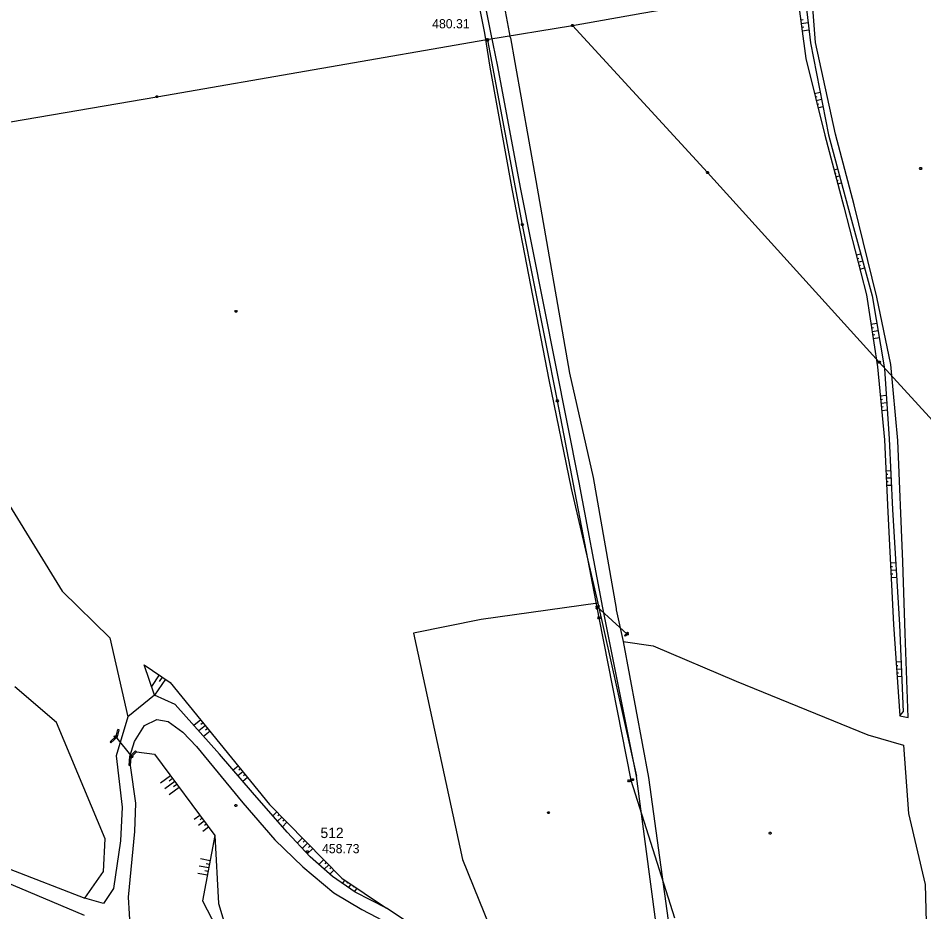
# Model space of a CAD drawing. Extents: x -664960 to -662754, y -993849 to -991145.
# Drawn here: x -664152.5 to -663855.3, y -993065.3 to -992772.1 of the extents above; entities that cross this region are included whole.
import ezdxf

# ---------------------------------------------------------------- set-up
doc = ezdxf.new("R2010")
doc.units = 0
for name, color, linetype in [('Vrstva 1', 7, 'Continuous'), ('Vrstva 13', 7, 'Continuous'), ('Vrstva 23', 7, 'Continuous'), ('Vrstva 24', 7, 'Continuous'), ('Vrstva 27', 7, 'Continuous'), ('Vrstva 37', 7, 'Continuous'), ('Vrstva 57', 7, 'Continuous'), ('Vrstva 63', 7, 'Continuous'), ('Vrstva 8', 7, 'Continuous')]:
    doc.layers.add(name, color=color, linetype=linetype)

msp = doc.modelspace()

# ---------------------------------------------------------------- linework, layer by layer
at = {"layer": 'Vrstva 13'}
for points in [[(-663856.195, -992821.143), (-663856.015, -992821.443), (-663856.195, -992821.743), (-663856.555, -992821.743), (-663856.735, -992821.443), (-663856.555, -992821.143), (-663856.195, -992821.143)], [(-664080.788, -992868.036), (-664080.608, -992868.336), (-664080.788, -992868.636), (-664081.148, -992868.636), (-664081.328, -992868.336), (-664081.148, -992868.036), (-664080.788, -992868.036)], [(-663978.312, -993032.479), (-663978.132, -993032.779), (-663978.312, -993033.079), (-663978.672, -993033.079), (-663978.852, -993032.779), (-663978.672, -993032.479), (-663978.312, -993032.479)], [(-663905.567, -993039.199), (-663905.387, -993039.499), (-663905.567, -993039.799), (-663905.927, -993039.799), (-663906.107, -993039.499), (-663905.927, -993039.199), (-663905.567, -993039.199)]]:
    msp.add_lwpolyline(points, dxfattribs=at)
at = {"layer": 'Vrstva 23'}
for points in [[(-663997.38, -992776.83), (-664005.01, -992738.66), (-664013.53, -992700.45), (-664027.03, -992643.59), (-664049.65, -992557.23), (-664058.31, -992527.13), (-664078.14, -992460.53), (-664096.77, -992402.28), (-664107.89, -992364.93), (-664112.84, -992348.94), (-664117.28, -992335.14), (-664119, -992322.82), (-664119, -992308.2)], [(-663990.89, -992778.63), (-663998.43, -992738.22), (-664009.08, -992695.49), (-664019.8, -992648.86), (-664043.31, -992556.7), (-664052, -992524.61), (-664073.04, -992455.33), (-664088.77, -992406.41), (-664100.89, -992363.53), (-664106.12, -992349.76), (-664111.81, -992331.24), (-664113.9, -992318.89), (-664113.87, -992308.88)], [(-663929.86, -993138.95), (-663931.93, -993130.37), (-663935.36, -993104.54), (-663943.29, -993068.58), (-663949.63, -993020.84), (-663960.66, -992965.6), (-663968.44, -992924.46), (-663987.68, -992827.67), (-663995.12, -992787.99), (-663997.38, -992776.83)], [(-663990.89, -992778.63), (-663989.48, -992786.64), (-663982.61, -992825.43), (-663971.53, -992888.56), (-663963.78, -992922.8), (-663956.22, -992965.82), (-663956.23, -992966.24), (-663953.96, -992976.6), (-663945.72, -993021.27), (-663939.17, -993068.14), (-663931.37, -993104), (-663922.1, -993138.98)]]:
    msp.add_lwpolyline(points, dxfattribs=at)
at = {"layer": 'Vrstva 24'}
for p, q in [((-663952.62, -992974.17), (-663962.52, -992965.24)), ((-664120.57, -993007.82), (-664115.13, -993014.42))]:
    msp.add_line(p, q, dxfattribs=at)
for points in [[(-663962.93, -992965.83), (-663961.97, -992964.76), (-663961.77, -992965.04), (-663962.65, -992966.03), (-663962.93, -992965.83)], [(-663962.855, -992965.342), (-663962.787, -992964.999), (-663962.453, -992964.897), (-663962.185, -992965.138), (-663962.253, -992965.481), (-663962.587, -992965.583), (-663962.855, -992965.342)], [(-663953.33, -992974.84), (-663953.59, -992974.69), (-663952.61, -992973.56), (-663952.29, -992973.72), (-663953.33, -992974.84)], [(-663952.955, -992974.272), (-663952.887, -992973.929), (-663952.553, -992973.827), (-663952.285, -992974.068), (-663952.353, -992974.411), (-663952.687, -992974.513), (-663952.955, -992974.272)], [(-664122.32, -993009.52), (-664120.25, -993007.7), (-664119.71, -993005.46)], [(-664122.32, -993009.52), (-664122.029, -993009.85), (-664119.855, -993007.938), (-664119.282, -993005.563), (-664119.71, -993005.46)], [(-664120.224, -993007.768), (-664120.341, -993008.098), (-664120.687, -993008.15), (-664120.916, -993007.872), (-664120.799, -993007.542), (-664120.453, -993007.49), (-664120.224, -993007.768)], [(-664115.56, -993017.28), (-664115.999, -993017.254), (-664115.829, -993014.333), (-664113.956, -993012.523), (-664113.65, -993012.84)], [(-664115.56, -993017.28), (-664115.4, -993014.53), (-664113.65, -993012.84)], [(-664114.784, -993014.368), (-664114.901, -993014.698), (-664115.247, -993014.75), (-664115.476, -993014.472), (-664115.359, -993014.142), (-664115.013, -993014.09), (-664114.784, -993014.368)]]:
    msp.add_lwpolyline(points, dxfattribs=at)
at = {"layer": 'Vrstva 27'}
for points in [[(-664107.68, -992994.21), (-664116.51, -993001.32), (-664120.25, -993014.1), (-664118.306, -993030.994), (-664118.882, -993042.04), (-664121.135, -993057.634), (-664124.418, -993062.517), (-664130.534, -993060.866)], [(-663988.75, -993092.41), (-664031.66, -993064.1), (-664041.89, -993058.81), (-664049.36, -993053.68), (-664056.66, -993047.27), (-664064.16, -993039.16), (-664075.63, -993026.18), (-664086.39, -993013.62), (-664100.97, -992997.24), (-664107.68, -992994.21)], [(-664115.829, -993014.333), (-664114.25, -993009.42), (-664110.98, -993004.16), (-664106.96, -993002.25), (-664103.2, -993002.9), (-664098.43, -993006.35), (-664093.97, -993011.05), (-664078.71, -993029.54), (-664068.24, -993041.69), (-664059.05, -993050.54), (-664048.87, -993059.03), (-664039.7, -993064.49), (-664034.92, -993067.05), (-664026.4, -993071.59), (-664028.58, -993076.81), (-664035.33, -993095.89)], [(-664115.645, -993071.429), (-664116.212, -993060.526), (-664114.152, -993038.9), (-664113.894, -993029.667), (-664115.56, -993017.28)]]:
    msp.add_lwpolyline(points, dxfattribs=at)
at = {"layer": 'Vrstva 37'}
msp.add_line((-663995.521, -992795.136), (-663995.521, -992795.136), dxfattribs=at)
for points in [[(-663970.4, -992774.27), (-663970.22, -992774.57), (-663970.4, -992774.87), (-663970.76, -992774.87), (-663970.94, -992774.57), (-663970.76, -992774.27), (-663970.4, -992774.27)], [(-663998.47, -992778.8), (-663998.29, -992779.1), (-663998.47, -992779.4), (-663998.83, -992779.4), (-663999.01, -992779.1), (-663998.83, -992778.8), (-663998.47, -992778.8)], [(-663998.32, -992779.06), (-663998.14, -992779.36), (-663998.32, -992779.66), (-663998.68, -992779.66), (-663998.86, -992779.36), (-663998.68, -992779.06), (-663998.32, -992779.06)], [(-664106.8, -992797.61), (-664106.62, -992797.91), (-664106.8, -992798.21), (-664107.16, -992798.21), (-664107.34, -992797.91), (-664107.16, -992797.61), (-664106.8, -992797.61)], [(-663926.11, -992822.45), (-663925.93, -992822.75), (-663926.11, -992823.05), (-663926.47, -992823.05), (-663926.65, -992822.75), (-663926.47, -992822.45), (-663926.11, -992822.45)], [(-663986.89, -992839.59), (-663986.71, -992839.89), (-663986.89, -992840.19), (-663987.25, -992840.19), (-663987.43, -992839.89), (-663987.25, -992839.59), (-663986.89, -992839.59)], [(-663869.78, -992884.69), (-663869.6, -992884.99), (-663869.78, -992885.29), (-663870.14, -992885.29), (-663870.32, -992884.99), (-663870.14, -992884.69), (-663869.78, -992884.69)], [(-663975.42, -992897.35), (-663975.24, -992897.65), (-663975.42, -992897.95), (-663975.78, -992897.95), (-663975.96, -992897.65), (-663975.78, -992897.35), (-663975.42, -992897.35)], [(-663961.73, -992968.56), (-663961.55, -992968.86), (-663961.73, -992969.16), (-663962.09, -992969.16), (-663962.27, -992968.86), (-663962.09, -992968.56), (-663961.73, -992968.56)], [(-663951.88, -993022.04), (-663951.7, -993022.34), (-663951.88, -993022.64), (-663952.24, -993022.64), (-663952.42, -993022.34), (-663952.24, -993022.04), (-663951.88, -993022.04)], [(-663950.71, -993021.67), (-663950.53, -993021.97), (-663950.71, -993022.27), (-663951.07, -993022.27), (-663951.25, -993021.97), (-663951.07, -993021.67), (-663950.71, -993021.67)]]:
    msp.add_lwpolyline(points, dxfattribs=at)
at = {"layer": 'Vrstva 57'}
for points in [[(-663970.58, -992774.57), (-663947.81, -992770.51), (-663896.715, -992761.596), (-663794.75, -992744.35), (-663665.051, -992722.016)], [(-663998.65, -992779.1), (-663970.58, -992774.57), (-663926.29, -992822.75), (-663869.96, -992884.99), (-663795.03, -992967.03), (-663725.94, -993043.04), (-663662.36, -993113.13), (-663592.02, -993190.94), (-663529.08, -993259.82), (-663458.89, -993337.24), (-663418.62, -993381.56)], [(-664180.69, -992810.49), (-664106.98, -992797.91), (-663998.65, -992779.1)], [(-663998.5, -992779.36), (-663987.07, -992839.89), (-663975.6, -992897.65), (-663961.91, -992968.86), (-663951.475, -993022.155), (-663937.17, -993067.28)]]:
    msp.add_lwpolyline(points, dxfattribs=at)
at = {"layer": 'Vrstva 63'}
for p, q in [((-663895.709, -992772.696), (-663894.96, -992772.596)), ((-663895.551, -992773.886), (-663893.314, -992773.588)), ((-663895.393, -992775.075), (-663894.653, -992774.977)), ((-663895.235, -992776.265), (-663893.028, -992775.971)), ((-663891.202, -992796.854), (-663889.356, -992796.4)), ((-663890.915, -992798.02), (-663890.319, -992797.873)), ((-663890.629, -992799.185), (-663888.894, -992798.758)), ((-663890.342, -992800.35), (-663889.783, -992800.213)), ((-663890.055, -992801.515), (-663888.433, -992801.116)), ((-663884.794, -992821.896), (-663883.588, -992821.573)), ((-663884.483, -992823.055), (-663884.081, -992822.947)), ((-663884.173, -992824.214), (-663882.96, -992823.889)), ((-663883.863, -992825.373), (-663883.458, -992825.265)), ((-663883.552, -992826.532), (-663882.333, -992826.206)), ((-663877.492, -992849.82), (-663876.011, -992849.439)), ((-663877.194, -992850.982), (-663876.695, -992850.854)), ((-663876.896, -992852.144), (-663875.379, -992851.755)), ((-663876.597, -992853.307), (-663876.087, -992853.175)), ((-663876.299, -992854.469), (-663874.748, -992854.071)), ((-663872.673, -992872.511), (-663870.724, -992872.215)), ((-663872.493, -992873.697), (-663871.837, -992873.598)), ((-663872.313, -992874.884), (-663870.322, -992874.581)), ((-663872.133, -992876.07), (-663871.463, -992875.968)), ((-663871.952, -992877.257), (-663869.92, -992876.948)), ((-663869.621, -992896.047), (-663867.614, -992895.852)), ((-663869.505, -992897.241), (-663868.849, -992897.177)), ((-663869.388, -992898.435), (-663867.456, -992898.248)), ((-663869.272, -992899.63), (-663868.641, -992899.568)), ((-663869.156, -992900.824), (-663867.298, -992900.643)), ((-663867.75, -992920.582), (-663866.177, -992920.509)), ((-663867.694, -992921.781), (-663867.17, -992921.757)), ((-663867.638, -992922.98), (-663866.063, -992922.906)), ((-663867.583, -992924.178), (-663867.058, -992924.154)), ((-663867.527, -992925.377), (-663865.949, -992925.304)), ((-663866.292, -992950.842), (-663864.551, -992950.756)), ((-663866.232, -992952.041), (-663865.649, -992952.012)), ((-663866.173, -992953.239), (-663864.411, -992953.152)), ((-663866.113, -992954.438), (-663865.523, -992954.409)), ((-663866.054, -992955.636), (-663864.271, -992955.548)), ((-663864.431, -992983.338), (-663862.815, -992983.225)), ((-663864.347, -992984.535), (-663863.819, -992984.498)), ((-663864.264, -992985.732), (-663862.706, -992985.624)), ((-664106.159, -992987.606), (-664108.673, -992991.374)), ((-664104.163, -992988.937), (-664107.68, -992994.21)), ((-664105.161, -992988.272), (-664106.165, -992989.777)), ((-663864.18, -992986.93), (-663863.671, -992986.894)), ((-663864.097, -992988.127), (-663862.597, -992988.022)), ((-663863.2, -993000.97), (-663862.07, -992999.67)), ((-664092.546, -993002.335), (-664094.804, -993004.168)), ((-664091.033, -993004.199), (-664093.206, -993005.962)), ((-664091.789, -993003.267), (-664092.527, -993003.866)), ((-664089.521, -993006.063), (-664091.609, -993007.757)), ((-664090.277, -993005.131), (-664090.987, -993005.706)), ((-664080.236, -993017.504), (-664081.903, -993018.858)), ((-664078.723, -993019.368), (-664080.341, -993020.681)), ((-664079.479, -993018.436), (-664080.026, -993018.88)), ((-664102.503, -993020.64), (-664105.791, -993023.074)), ((-664101.789, -993021.605), (-664102.884, -993022.415)), ((-664077.211, -993021.231), (-664078.779, -993022.504)), ((-664077.967, -993020.3), (-664078.498, -993020.73)), ((-664101.075, -993022.569), (-664104.363, -993025.003)), ((-664099.647, -993024.498), (-664102.935, -993026.932)), ((-664100.361, -993023.534), (-664101.456, -993024.344)), ((-664092.866, -993033.659), (-664094.742, -993035.048)), ((-664067.64, -993032.508), (-664068.923, -993033.77)), ((-664065.957, -993034.218), (-664067.331, -993035.571)), ((-664066.799, -993033.363), (-664067.241, -993033.799)), ((-664091.438, -993035.588), (-664093.314, -993036.977)), ((-664092.152, -993034.624), (-664092.777, -993035.086)), ((-664090.724, -993036.553), (-664091.349, -993037.015)), ((-664064.273, -993035.929), (-664065.74, -993037.372)), ((-664065.115, -993035.074), (-664065.588, -993035.539)), ((-664090.01, -993037.517), (-664091.886, -993038.906)), ((-664059.205, -993041.078), (-664060.87, -993042.717)), ((-664057.522, -993042.789), (-664059.24, -993044.48)), ((-664058.363, -993041.933), (-664058.927, -993042.488)), ((-664055.838, -993044.499), (-664057.61, -993046.243)), ((-664056.68, -993043.644), (-664057.261, -993044.216)), ((-664089.505, -993048.545), (-664092.589, -993047.963)), ((-664052.219, -993048.176), (-664053.827, -993049.758)), ((-664051.377, -993049.031), (-664051.892, -993049.537)), ((-664089.95, -993050.903), (-664093.034, -993050.321)), ((-664090.173, -993052.082), (-664091.2, -993051.888)), ((-664089.728, -993049.724), (-664090.755, -993049.53)), ((-664050.536, -993049.886), (-664052.018, -993051.346)), ((-664048.852, -993051.597), (-664050.21, -993052.933)), ((-664049.694, -993050.741), (-664050.167, -993051.207)), ((-664090.395, -993053.261), (-664093.479, -993052.68)), ((-664045.335, -993054.849), (-664046.072, -993055.938)), ((-664044.341, -993055.522), (-664044.588, -993055.886)), ((-664043.347, -993056.194), (-664044.093, -993057.297)), ((-664042.353, -993056.866), (-664042.603, -993057.236)), ((-664041.359, -993057.539), (-664042.115, -993058.656))]:
    msp.add_line(p, q, dxfattribs=at)
for points in [[(-664119, -992322.82), (-664118.91, -992334.49), (-664115.54, -992347.49), (-664110.14, -992365.57), (-664098.26, -992403.07), (-664082.2, -992456.72), (-664059.59, -992531.27), (-664053.27, -992554.58), (-664029.83, -992642.01), (-664015.6, -992700.81), (-664007.21, -992738.41), (-663999.43, -992777.06)], [(-663896.853, -992764.097), (-663894.02, -992785.4), (-663887.84, -992810.52), (-663881.55, -992834.01), (-663874.13, -992862.92), (-663870.55, -992886.49), (-663868.22, -992910.45), (-663867.12, -992934.15), (-663865.29, -992971.03), (-663863.2, -993000.97)], [(-663894.186, -992766.334), (-663892.51, -992780.28), (-663886.62, -992810.38), (-663880.33, -992833.6), (-663872.25, -992863.23), (-663868.19, -992887.13), (-663866.67, -992910.15), (-663865.57, -992933.27), (-663863.36, -992971.18), (-663862.07, -992999.67)], [(-663863.2, -993000.97), (-663860.48, -993001.51), (-663861.41, -992974.03), (-663862.22, -992950.48), (-663863.91, -992910.69), (-663866.12, -992885.74), (-663870.74, -992863.63), (-663878.18, -992833.43), (-663884.33, -992810.2), (-663890.88, -992780.17), (-663891.988, -992765.751)], [(-663999.43, -992777.06), (-663997.71, -992788.2), (-663990.37, -992828.73), (-663978.4, -992890.81), (-663971.05, -992926.42), (-663962.31, -992964.08), (-663949.63, -993020.84)], [(-664223.88, -992818.39), (-664216.36, -992828.15), (-664200.78, -992855.06), (-664185.8, -992877.59), (-664168.39, -992905.62), (-664155.33, -992931.98), (-664138.07, -992960.07), (-664122.36, -992975.38), (-664116.51, -993001.32)], [(-664130.678, -993066.532), (-664156.854, -993055.457), (-664171.024, -993052.13), (-664176.885, -993051.684), (-664184.1, -993048.332), (-664208.518, -993025.831), (-664225.229, -993010.614), (-664240.873, -992991.914), (-664254.272, -992978.277), (-664260.266, -992968.033), (-664273.375, -992953.363), (-664289.388, -992940.125), (-664310.911, -992926.141), (-664336.284, -992914.557), (-664354.639, -992907.946), (-664373.632, -992901.138), (-664389.166, -992898.314), (-664395.725, -992897.751), (-664408.092, -992896.554)], [(-663962.31, -992964.08), (-664000.53, -992969.44), (-664022.8, -992973.93), (-664006.71, -993048.08), (-663988.75, -993092.41)], [(-663953.96, -992976.6), (-663944.14, -992978), (-663916.87, -992989.68), (-663873.66, -993007.23), (-663861.96, -993010.62), (-663860.36, -993033.02), (-663854.94, -993056.31), (-663854.48, -993072.82), (-663862.23, -993074.18), (-663868.63, -993079.01), (-663886.15, -993085.85), (-663925.46, -993100.87), (-663931.37, -993104)], [(-664107.68, -992994.21), (-664111.16, -992984.27), (-664102.54, -992990.02), (-664070.03, -993030.08), (-664046.28, -993054.21), (-664031.66, -993064.1)], [(-664130.534, -993060.866), (-664124.505, -993052.08), (-664123.862, -993041.315), (-664139.826, -993003.204), (-664153.498, -992991.506)], [(-664113.65, -993012.84), (-664107.7, -993013.62), (-664087.95, -993040.3), (-664086.68, -993062.58), (-664080.08, -993084.61), (-664075.12, -993097.66), (-664076.38, -993116.4), (-664078.34, -993140.71), (-664078.91, -993164.26), (-664075.53, -993183.68), (-664078.59, -993206.08)], [(-664080.88, -993030.11), (-664080.7, -993030.41), (-664080.88, -993030.71), (-664081.24, -993030.71), (-664081.42, -993030.41), (-664081.24, -993030.11), (-664080.88, -993030.11)], [(-664087.95, -993040.3), (-664091.98, -993061.66), (-664080.08, -993084.61)], [(-664155.408, -993051.184), (-664130.534, -993060.866)]]:
    msp.add_lwpolyline(points, dxfattribs=at)
at = {"layer": 'Vrstva 8'}
msp.add_lwpolyline([(-664057.38, -993045.3), (-664057.2, -993045.6), (-664057.38, -993045.9), (-664057.74, -993045.9), (-664057.92, -993045.6), (-664057.74, -993045.3), (-664057.38, -993045.3)], dxfattribs=at)

# ---------------------------------------------------------------- texts
at = {"layer": 'Vrstva 1'}
msp.add_text('512', height=3.4, dxfattribs=at).set_placement((-664053.282, -993041.094))
at = {"layer": 'Vrstva 63'}
for s, p in [('480.31', (-664016.627, -992775.466)), ('458.73', (-664052.758, -993046.074))]:
    msp.add_text(s, height=3, dxfattribs=at).set_placement(p)

doc.saveas('drawing.dxf')
